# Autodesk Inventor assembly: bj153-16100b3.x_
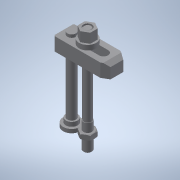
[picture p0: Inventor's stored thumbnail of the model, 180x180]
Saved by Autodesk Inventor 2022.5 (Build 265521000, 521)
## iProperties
Part Number: bj153-16100b3.x_
Material: 一般
Document SubType Name: Assembly
Designer: ImaoCorp
Sending System: SOLIDWORKS 2017-2017317
MC: AMD64
MC_MODEL: Intel64 Family 6 Model 60 Stepping 3, GenuineIntel
OS: Windows_NT
FRU: Parasolid Version 29.0, build 201,  4-17-2017
FORMAT: text
GUISE: transmit
KEY: bj153-16100b3
FILE: bj153-16100b3.x_t
DATE: Fri Mar 15 10:23:29 2019
Author: ImaoCorp
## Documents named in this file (6)
- X:\14_SW2022-Inv2022\00_全2023-1023新製品(TCC)まで\b\bj153-16100b3\BJ153-16100B3.iam
- X:\14_SW2022-Inv2022\00_全2023-1023新製品(TCC)まで\b\bj153-16100b3\bj153-16100b3_01.ipt
- X:\14_SW2022-Inv2022\00_全2023-1023新製品(TCC)まで\b\bj153-16100b3\bj153-16100b3_02.ipt
- X:\14_SW2022-Inv2022\00_全2023-1023新製品(TCC)まで\b\bj153-16100b3\bj153-16100b3_03.ipt
- X:\14_SW2022-Inv2022\00_全2023-1023新製品(TCC)まで\b\bj153-16100b3\bj153-16100b3_04.ipt
- X:\14_SW2022-Inv2022\00_全2023-1023新製品(TCC)まで\b\bj153-16100b3\bj153-16100b3_05.ipt
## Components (5 placed, 5 different names)
1. bj153-16100b3_01
2. bj153-16100b3_02
3. bj153-16100b3_03
4. bj153-16100b3_04
5. bj153-16100b3_05
